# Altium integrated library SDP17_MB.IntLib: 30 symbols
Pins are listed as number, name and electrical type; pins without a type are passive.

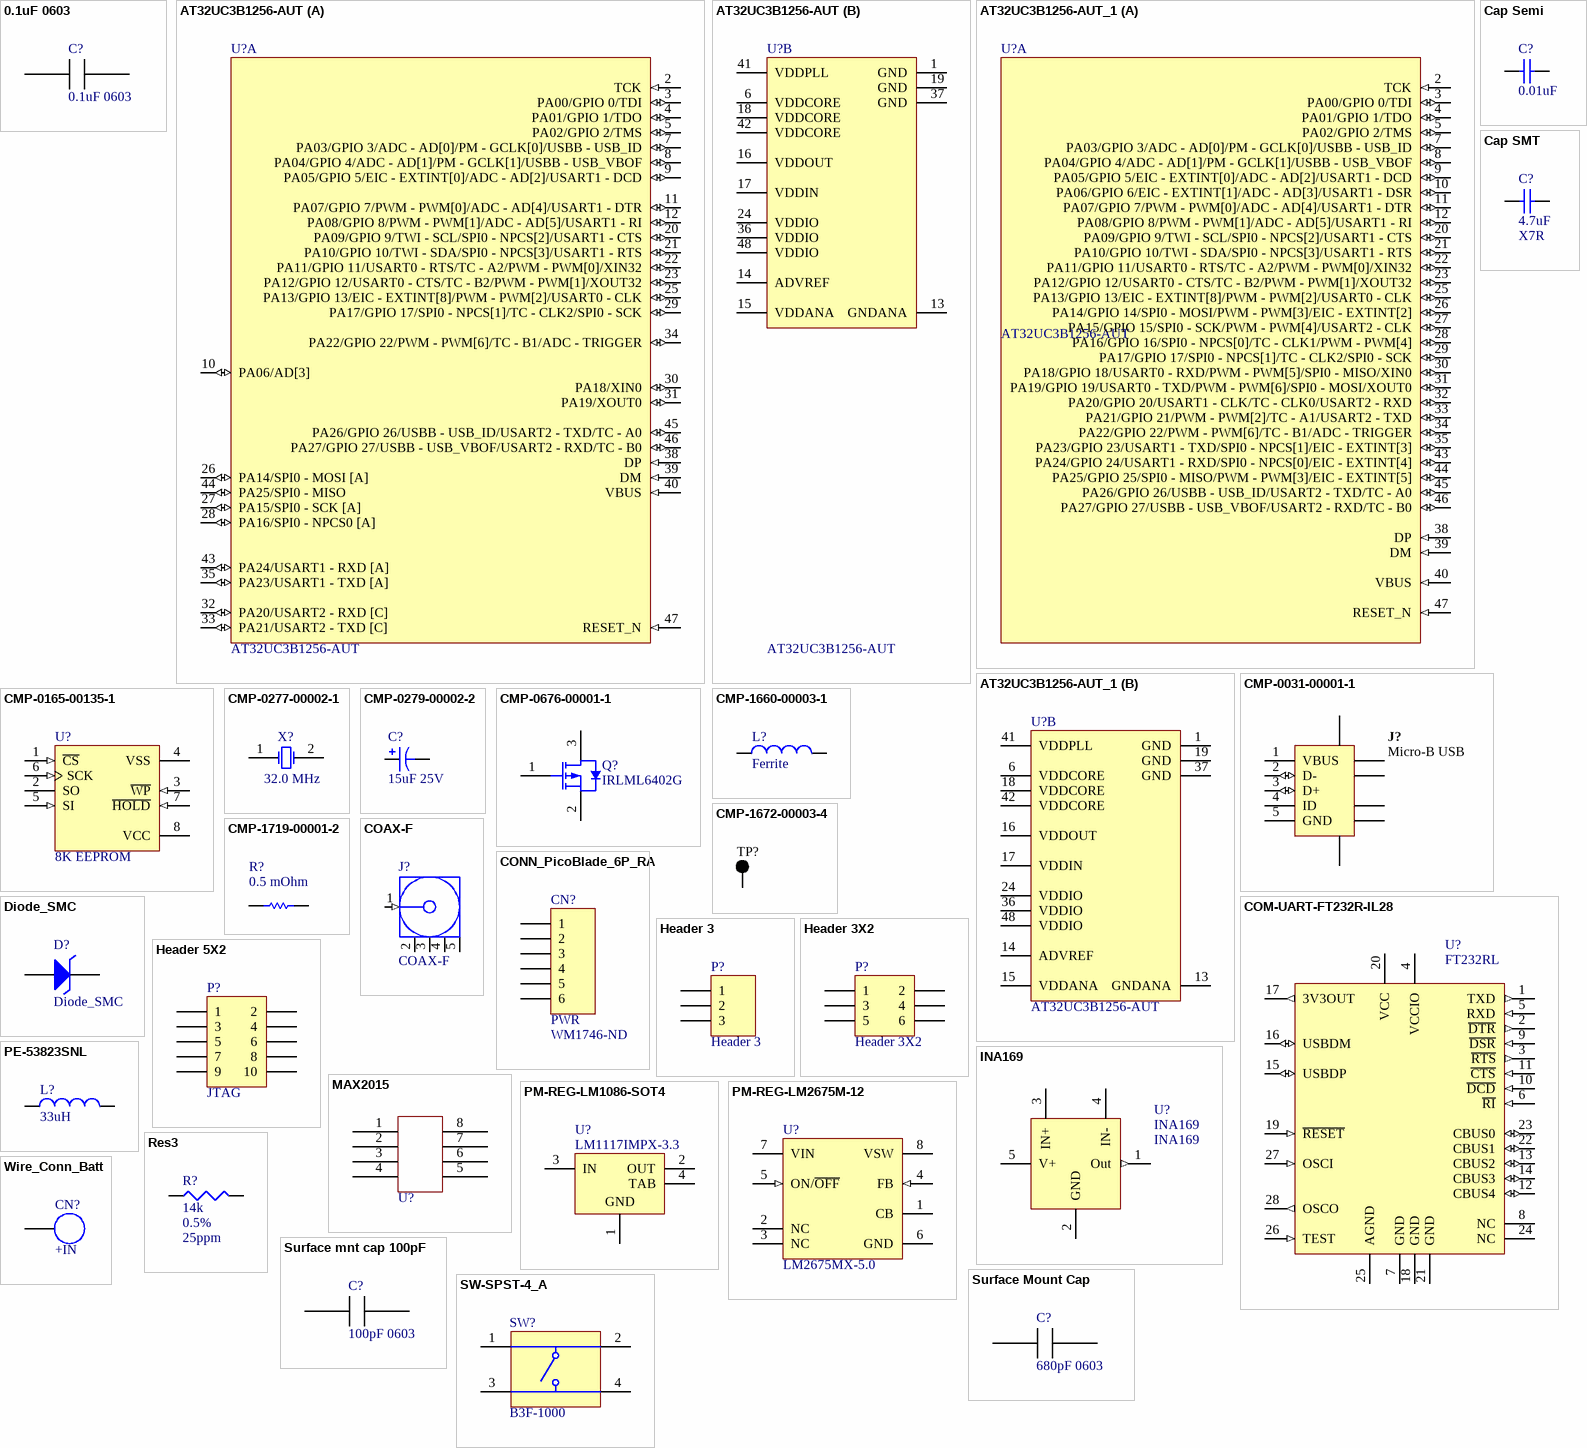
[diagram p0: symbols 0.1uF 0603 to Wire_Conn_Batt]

## 0.1uF 0603
designator C?
footprint Surface mnt Cap (0.1uF 0603)
pins: 1, 2

## AT32UC3B1256-AUT
designator U?
32-bit AVR UC3 B Series Microcontroller, 256KB Flash, 32KB SRAM, 28 GPIO pins, Industrial Grade, 48-Pin TQFP, Tray
footprint TQFP48_N (Thin QFP, 48-Leads, Body 7x7mm, Pitch 0.5mm, IPC Medium Density)
footprint TQFP48_L (Thin QFP, 48-Leads, Body 7x7mm, Pitch 0.5mm, IPC High Density)
footprint TQFP48_M (Thin QFP, 48-Leads, Body 7x7mm, Pitch 0.5mm, IPC Low Density)
part A pins: 2 TCK (in), 3 PA00/GPIO 0/TDI (io), 4 PA01/GPIO 1/TDO (io), 5 PA02/GPIO 2/TMS (io), 7 PA03/GPIO 3/ADC - AD[0]/PM - GCLK[0]/USBB - USB_ID (io), 8 PA04/GPIO 4/ADC - AD[1]/PM - GCLK[1]/USBB - USB_VBOF (io), 9 PA05/GPIO 5/EIC - EXTINT[0]/ADC - AD[2]/USART1 - DCD (io), 10 PA06/AD[3] (io), 11 PA07/GPIO 7/PWM - PWM[0]/ADC - AD[4]/USART1 - DTR (io), 12 PA08/GPIO 8/PWM - PWM[1]/ADC - AD[5]/USART1 - RI (io), 20 PA09/GPIO 9/TWI - SCL/SPI0 - NPCS[2]/USART1 - CTS (io), 21 PA10/GPIO 10/TWI - SDA/SPI0 - NPCS[3]/USART1 - RTS (io), 22 PA11/GPIO 11/USART0 - RTS/TC - A2/PWM - PWM[0]/XIN32 (io), 23 PA12/GPIO 12/USART0 - CTS/TC - B2/PWM - PWM[1]/XOUT32 (io), 25 PA13/GPIO 13/EIC - EXTINT[8]/PWM - PWM[2]/USART0 - CLK (io), 26 PA14/SPI0 - MOSI [A] (io), 27 PA15/SPI0 - SCK [A] (io), 28 PA16/SPI0 - NPCS0 [A] (io), 29 PA17/GPIO 17/SPI0 - NPCS[1]/TC - CLK2/SPI0 - SCK (io), 30 PA18/XIN0 (io), 31 PA19/XOUT0 (io), 32 PA20/USART2 - RXD [C] (io), 33 PA21/USART2 - TXD [C] (io), 34 PA22/GPIO 22/PWM - PWM[6]/TC - B1/ADC - TRIGGER (io), 35 PA23/USART1 - TXD [A] (io), 38 DP (in), 39 DM (in), 40 VBUS (in), 43 PA24/USART1 - RXD [A] (io), 44 PA25/SPI0 - MISO (io), 45 PA26/GPIO 26/USBB - USB_ID/USART2 - TXD/TC - A0 (io), 46 PA27/GPIO 27/USBB - USB_VBOF/USART2 - RXD/TC - B0 (io), 47 RESET_N (in)
part B pins: 1 GND (power), 6 VDDCORE (power), 13 GNDANA (power), 14 ADVREF (power), 15 VDDANA (power), 16 VDDOUT (power), 17 VDDIN (power), 18 VDDCORE (power), 19 GND (power), 24 VDDIO (power), 36 VDDIO (power), 37 GND (power), 41 VDDPLL (power), 42 VDDCORE (power), 48 VDDIO (power)

## AT32UC3B1256-AUT_1
designator U?, comment AT32UC3B1256-AUT
32-bit AVR UC3 B Series Microcontroller, 256KB Flash, 32KB SRAM, 28 GPIO pins, Industrial Grade, 48-Pin TQFP, Tray
footprint TQFP48_N (Thin QFP, 48-Leads, Body 7x7mm, Pitch 0.5mm, IPC Medium Density)
footprint TQFP48_L (Thin QFP, 48-Leads, Body 7x7mm, Pitch 0.5mm, IPC High Density)
footprint TQFP48_M (Thin QFP, 48-Leads, Body 7x7mm, Pitch 0.5mm, IPC Low Density)
part A pins: 2 TCK (in), 3 PA00/GPIO 0/TDI (io), 4 PA01/GPIO 1/TDO (io), 5 PA02/GPIO 2/TMS (io), 7 PA03/GPIO 3/ADC - AD[0]/PM - GCLK[0]/USBB - USB_ID (io), 8 PA04/GPIO 4/ADC - AD[1]/PM - GCLK[1]/USBB - USB_VBOF (io), 9 PA05/GPIO 5/EIC - EXTINT[0]/ADC - AD[2]/USART1 - DCD (io), 10 PA06/GPIO 6/EIC - EXTINT[1]/ADC - AD[3]/USART1 - DSR (io), 11 PA07/GPIO 7/PWM - PWM[0]/ADC - AD[4]/USART1 - DTR (io), 12 PA08/GPIO 8/PWM - PWM[1]/ADC - AD[5]/USART1 - RI (io), 20 PA09/GPIO 9/TWI - SCL/SPI0 - NPCS[2]/USART1 - CTS (io), 21 PA10/GPIO 10/TWI - SDA/SPI0 - NPCS[3]/USART1 - RTS (io), 22 PA11/GPIO 11/USART0 - RTS/TC - A2/PWM - PWM[0]/XIN32 (io), 23 PA12/GPIO 12/USART0 - CTS/TC - B2/PWM - PWM[1]/XOUT32 (io), 25 PA13/GPIO 13/EIC - EXTINT[8]/PWM - PWM[2]/USART0 - CLK (io), 26 PA14/GPIO 14/SPI0 - MOSI/PWM - PWM[3]/EIC - EXTINT[2] (io), 27 PA15/GPIO 15/SPI0 - SCK/PWM - PWM[4]/USART2 - CLK (io), 28 PA16/GPIO 16/SPI0 - NPCS[0]/TC - CLK1/PWM - PWM[4] (io), 29 PA17/GPIO 17/SPI0 - NPCS[1]/TC - CLK2/SPI0 - SCK (io), 30 PA18/GPIO 18/USART0 - RXD/PWM - PWM[5]/SPI0 - MISO/XIN0 (io), 31 PA19/GPIO 19/USART0 - TXD/PWM - PWM[6]/SPI0 - MOSI/XOUT0 (io), 32 PA20/GPIO 20/USART1 - CLK/TC - CLK0/USART2 - RXD (io), 33 PA21/GPIO 21/PWM - PWM[2]/TC - A1/USART2 - TXD (io), 34 PA22/GPIO 22/PWM - PWM[6]/TC - B1/ADC - TRIGGER (io), 35 PA23/GPIO 23/USART1 - TXD/SPI0 - NPCS[1]/EIC - EXTINT[3] (io), 38 DP (in), 39 DM (in), 40 VBUS (in), 43 PA24/GPIO 24/USART1 - RXD/SPI0 - NPCS[0]/EIC - EXTINT[4] (io), 44 PA25/GPIO 25/SPI0 - MISO/PWM - PWM[3]/EIC - EXTINT[5] (io), 45 PA26/GPIO 26/USBB - USB_ID/USART2 - TXD/TC - A0 (io), 46 PA27/GPIO 27/USBB - USB_VBOF/USART2 - RXD/TC - B0 (io), 47 RESET_N (in)
part B pins: 1 GND (power), 6 VDDCORE (power), 13 GNDANA (power), 14 ADVREF (power), 15 VDDANA (power), 16 VDDOUT (power), 17 VDDIN (power), 18 VDDCORE (power), 19 GND (power), 24 VDDIO (power), 36 VDDIO (power), 37 GND (power), 41 VDDPLL (power), 42 VDDCORE (power), 48 VDDIO (power)

## Cap Semi
designator C?  value 0.01uF  (hidden comment: Cap Semi)
Capacitor (Semiconductor SIM Model)
footprint C1206 (Chip Capacitor, Body 3.2x1.6mm, IPC High Density)
footprint 0402 (Chip Capacitor, Body 1.0x0.5mm, IPC High Density)
footprint C2512 (Chip Capacitor, Body 2.54x1.27mm, IPC High Density)
footprint 1608[0603] (Chip Capacitor, Body 1.6x0.8mm, IPC High Density)
footprint C1210 (Chip Capacitor, Body 3.2x2.5mm, IPC High Density)
simulation model CAP (Semiconductor Capacitor)
signal-integrity model Cap Semi
pins: 1, 2

## Cap SMT
designator C?  value 4.7uF  Tempco: X7R
Capacitor (Semiconductor SIM Model)
footprint C1206 (Chip Capacitor, Body 3.2x1.6mm, IPC High Density)
footprint 0402 (Chip Capacitor, Body 1.0x0.5mm, IPC High Density)
footprint C2512 (Chip Capacitor, Body 2.54x1.27mm, IPC High Density)
footprint 1608[0603] (Chip Capacitor, Body 1.6x0.8mm, IPC High Density)
footprint C1210 (Chip Capacitor, Body 3.2x2.5mm, IPC High Density)
simulation model CAP (Semiconductor Capacitor)
signal-integrity model Cap Semi
footprint 2012[0805] (Chip Resistor; Body 2.0 x 1.3 mm (LxW typ))
pins: 1, 2

## CMP-0031-00001-1
designator J?, comment Micro-B USB
Connector; USBMicro-B,Reverse type, SMT; 5 Position; Right Angle; PartNumber: ZX62R-B-5P(30)
footprint HIRO-ZX62R-B-5P_V (USB Micro-B R/A Connector)
pins: 1 VBUS (power), 2 D- (io), 3 D+ (io), 4 ID, 5 GND (power), 6 SHLD, 7 SHLD, 8 SHLD, 9 SHLD, 10 SHLD, 11 SHLD

## CMP-0165-00135-1
designator U?, comment 8K EEPROM
8K SPI Bus Serial EEPROM, 8-Pin SOIC, Tape and Reel; Manufacture PN: CAT25080VI-GT3; ComponentAvailability: Unknown. Contact manufacturer to determine status.
footprint SOIC-SN8_N (SOIC, 8-Leads, Body 4.9x3.8mm, Pitch 1.27mm, IPC Medium Density)
footprint SOIC-SN8_M (SOIC, 8-Leads, Body 4.9x3.8mm, Pitch 1.27mm, IPC Low Density)
footprint SOIC-SN8_L (SOIC, 8-Leads, Body 4.9x3.8mm, Pitch 1.27mm, IPC High Density)
pins: 1 ~{CS} (in), 2 SO (hiz), 3 ~{WP} (in), 4 VSS (power), 5 SI (in), 6 SCK (in), 7 ~{HOLD} (in), 8 VCC (power)

## CMP-0277-00002-1
designator X?, comment Frequency: 32.0 MHz  (hidden comment: ABLS2-32.000MHZ-D4YF-T)
Low Profile Surface Mount Microprocessor Crystal, 4.096 MHz +/-30 ppm, 180 Ohm, -40 to 85 degC, 2-Pin 11.4 x 4.7 x 3.3 mm SMD, RoHS, Tape and Reel; Manufacturer: Abracon; Operation Mode: Fundamental or 3rd Overtone; Shunt Capacitance: 7 pF Max.; ESR: 180 Ohm; Load Capacitance: 18 pF
footprint ABRA-ABLS2-2_V (SMD, 2-Leads, Body 11.4x4.7mm, Height 3.3mm)
pins: 1 X1, 2 X2

## CMP-0279-00002-2
designator C?, comment 15uF 25V
15µF ±10% Molded Tantalum Capacitors 25V 2312 (6032 Metric) 100 mOhm; PartNumber: TPSD156K025S0100; Manufacturer: AVX; Polarity: Polarized
footprint AVX-CAPC7343_V (SMT Capacitor, 2 Leads, Body 7.3x4.3mm)
pins: 1, 2

## CMP-0676-00001-1
designator Q?, comment IRLML6402G
HEXFET Power MOSFET, P-Channel, -20 V VDSS, 0.065 Ohm RDS, 3-Pin SOT23, RoHS, Tape and Reel; PartNumber: IRLML6402GPbF; Manufacturer: International Rectifier; ISM (Max.): -22 A; QRR (Typ.): 11 nC; VSD (Max.): -1.2 V; IS (Max.): -1.3 A; VGS(TH): -0.4 to -1.2 V; V(BR)DSS (Min.): -20 V; TRR (Typ.): 29 ns
footprint INTR-SOT-23-3_V (SOT23, 3-Leads, Body 2.92x1.3mm, Pitch 1.9mm)
pins: 1 G, 2 S, 3 D

## CMP-1660-00003-1
designator L?, comment Ferrite
Chip Inductor, 21 Ohm, +/- 30%, 6 A, -40 to 125 degC, 0805 (2012 Metric), RoHS, Tape and Reel; Current Rating: 6 A; Resistance: 4 mohm; Case\Package: 0805; Impedance: 21 Ohm
footprint INDC2013X105X50LL20T30 (Chip Inductor, 2-Leads, Body 2.2x1.45mm, IPC High Density)
footprint INDC2013X105X50ML20T30 (Chip Inductor, 2-Leads, Body 2.2x1.45mm, IPC Low Density)
footprint INDC2013X105X50NL20T30 (Chip Inductor, 2-Leads, Body 2.2x1.45mm, IPC Medium Density)
pins: 1, 2

## CMP-1672-00003-4
designator TP?, comment ISENSE  (value not drawn)
Test Point, Black, Through Hole, RoHS, Bulk; Manufacturer: Keystone
footprint KSTN-5011_V (Test Point, Dia 3.17mm)
pins: 1

## CMP-1719-00001-2
designator R?, comment Resistance: 0.5 mOhm  (hidden comment: CSS2725FTL500CT-ND)
Chip Resistor, 0.5 mOhm, +/- 1%, 4 W, -55 to 225 degC, 2725 (6865 Metric), RoHS, Tape and Reel
footprint STAC-CSS2725-099H_V (Chip Resistor, 2-Leads, Body 7.06x6.7mm)
pins: 1, 2

## COAX-F
designator J?
RF Coaxial PCB Connector, MCX; Thru-Hole, Right-Angle Mount Socket, Blunt Post Terminal, 50 Ohm Impedance; PCB_Layout: Complies with manufacturer's recommendation.; DrillSize: Corresponds to nominal value.
footprint MCX5.08-H5 (Connector; RF Coaxial, MCX, Thru-Hole; 5 Position; Right-Angle)
pins: 1 Signal (in) "Signal Pin", 2 GND (power), 3 GND (power), 4 GND (power), 5 GND (power)

## COM-UART-FT232R-IL28
designator U?, comment FT232RL
USB UART Asynchronous Serial Data Transfer Chip, 28-pin SSOP, Tube; PartNumber: FT232RL-Tube; Manufacturer: FTDI
footprint SSOP-28_N (SOP, 28-Leads, Body 10.2x5.3mm, Pitch 0.65mm, IPC Medium Density)
footprint SSOP-28_L (SOP, 28-Leads, Body 10.2x5.3mm, Pitch 0.65mm, IPC High Density)
footprint SSOP-28_M (SOP, 28-Leads, Body 10.2x5.3mm, Pitch 0.65mm, IPC Low Density)
pins: 1 TXD (out), 2 ~{DTR} (out), 3 ~{RTS} (out), 4 VCCIO (power), 5 RXD (in), 6 ~{RI} (in), 7 GND (power), 8 NC, 9 ~{DSR} (in), 10 ~{DCD} (in), 11 ~{CTS} (in), 12 CBUS4 (io), 13 CBUS2 (io), 14 CBUS3 (io), 15 USBDP (io), 16 USBDM (io), 17 3V3OUT (out), 18 GND (power), 19 ~{RESET} (in), 20 VCC (power), 21 GND (power), 22 CBUS1 (io), 23 CBUS0 (io), 24 NC, 25 AGND (power), 26 TEST (in), 27 OSCI (in), 28 OSCO (out)

## CONN_PicoBlade_6P_RA
designator CN?, comment PWR  Supplier Part Number 1: WM1746-ND
PicoBlade right angle through hole conn; Manufacturer: Molex, LLC; Manufacturer Part Number: 0530480610; Connector Type: Header; Pitch - Mating: 0.049" (1.25mm); Shrouding: Shrouded - 4 Wall; Number of Positions: 6; Number of Positions Loaded: All
signal-integrity model Connector
footprint CONN_PICOBLADE_6P
pins: 1, 2, 3, 4, 5, 6

## Diode_SMC
designator D?
DO-214-AB / SMC SCHOTTKY
footprint SMC (DO-214-AB/SMC; 2 C-Bend Leads; Body 7.9 x 5.9 mm, inc. leads (LxW))
simulation model DIODE (Diode)
signal-integrity model Diode
pins: 1 A, 2 K

## Header 3
designator P?
Header, 3-Pin
footprint HDR1X3 (Connector; Header; 3 Position)
signal-integrity model Connector
pins: 1, 2, 3

## Header 3X2
designator P?
Header, 3-Pin, Dual row
footprint HDR2X3 (Connector; Header; 3x2 Position)
signal-integrity model Connector
pins: 1, 2, 3, 4, 5, 6

## Header 5X2
designator P?, comment JTAG
Header, 5-Pin, Dual row
footprint HDR2X5 (Connector; Header; 5x2 Position)
signal-integrity model Connector
pins: 1, 2, 3, 4, 5, 6, 7, 8, 9, 10

## INA169
designator U?
Manufacturer: Texas Instruments; Manufacturer Part Number: INA169NA/250; Function: Current Monitor; Sensing Method: High-Side; Accuracy: ±0.5%; Voltage - Input: 2.7 V ~ 60 V
footprint SOT23-5BL (SOT23, 5-Leads, Body 2.9x1.6mm, Pitch 0.95mm, Lead Span 2.8mm, IPC High Density)
pins: 1 Out (out), 2 GND, 3 IN+, 4 IN-, 5 V+ (power)

## MAX2015
designator U?  (value not drawn)
IC
footprint TSOP65P490X110-8N (TSOP, 8-Leads, Body 3.00x3.00mm, Pitch 0.65mm, IPC Medium Density)
pins: 1, 2, 3, 4, 5, 6, 7, 8

## PE-53823SNL
designator L?  Supplier Part Number 1: 33uH  (hidden comment: PE-53823SNL)
FIXED IND 38UH 1.2A 100 MOHM SMD; Manufacturer: Pulse Electronics Corporation; Type: Toroidal; Inductance: 38µH; Shielding: Unshielded
footprint IND_TOROID_SMT_PULSE (LCI-37 PACKAGE)
pins: 1, 2

## PM-REG-LM1086-SOT4
designator U?, comment LM1117IMPX-3.3
800mA Low-Dropout Linear Regulator, 4-pin SOT-223; Manufacturer: National Semiconductor; CompType: LDO IC; PowerWise: N; High-Reliability: Y; PackageTopMarking: XYTT*N05B
footprint MP04A_M (SOT223, 4-Leads, Body 6.5x3.5mm, Pitch 2.3mm, Lead Span 7mm, IPC Low Density)
footprint MP04A_L (SOT223, 4-Leads, Body 6.5x3.5mm, Pitch 2.3mm, Lead Span 7mm, IPC High Density)
footprint MP04A_N (SOT223, 4-Leads, Body 6.5x3.5mm, Pitch 2.3mm, Lead Span 7mm, IPC Medium Density)
pins: 1 GND (power), 2 OUT (power), 3 IN (power), 4 TAB (power)

## PM-REG-LM2675M-12
designator U?, comment LM2675MX-5.0
SIMPLE SWITCHER® Power Converter High Efficiency 1A Step-Down Voltage Regulator, 8-pin Narrow SOIC; Manufacturer: National Semiconductor; PowerWise: N; PackageTopMarking: NSZXTT*2675*M5.0
footprint M08A_L (SOIC, 8-Leads, Body 4.9x3.9mm, Pitch 1.27mm, IPC High Density)
footprint M08A_N (SOIC, 8-Leads, Body 4.9x3.9mm, Pitch 1.27mm, IPC Medium Density)
footprint M08A_M (SOIC, 8-Leads, Body 4.9x3.9mm, Pitch 1.27mm, IPC Low Density)
pins: 1 CB, 2 NC, 3 NC, 4 FB (in), 5 ON/~{OFF} (in), 6 GND (power), 7 VIN (power), 8 VSW (power)

## Res3
designator R?  value 14k  Tol: 0.5%  Tempco: 25ppm  (hidden comment: Res3)
Resistor
footprint J1-0603 (Chip Resistor, Body 1.6x0.8mm, IPC High Density)
footprint 14-1210 (Chip Resistor, Body 3.2x2.5mm, IPC High Density)
footprint 12Z-2010 (Chip Resistor, Body 5.0x2.5mm, IPC High Density)
footprint RESC6332 (Chip Resistor, Body 6.3x3.2mm, IPC High Density)
simulation model RESISTOR (Resistor)
signal-integrity model Res
pins: 1, 2

## Surface mnt cap 100pF
designator C?, comment 100pF 0603
footprint Surface mnt capacitor (100pF 0603)
pins: 1, 2

## Surface Mount Cap
designator C?, comment 680pF 0603
Surface Mount Capacitor
footprint CAP 680pF 0603 (Chip Capacitor, 2-Leads, Body 1.60x0.80mm, IPC Medium Density)
pins: 1, 2

## SW-SPST-4_A
designator SW?, comment B3F-1000
Tactile Switch, SPST-NO, 0.05 A, 5 to 24 V, -25 to 70 degC, 4-Pin THD, RoHS, Bulk; Shielding: Shielded; Gender: Female; Capacitance: -45 f; Voltage Rating: 150 V; Current Rating: 1.5 A
footprint OMRON-B3F-1000-4_V (TH, 4-Leads, Body 6x6mm)
pins: 1, 2, 3, 4

## Wire_Conn_Batt
designator CN?, comment +IN
footprint WireConn_120mil
pins: 1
